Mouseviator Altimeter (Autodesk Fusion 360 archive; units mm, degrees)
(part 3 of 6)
sketch "Sketch2" plane through (0, 18.05, 0) normal (0, -1, 0) x axis (1, 0, 0)
  line L1 (-13.7221, 22.981) -> (-13.791, 23.1632)
  line L2 (-13.6429, 22.7949) -> (-13.7221, 22.981)
  line L3 (-13.562, 22.6247) -> (-13.6429, 22.7949)
  line L4 (-13.4808, 22.471) -> (-13.562, 22.6247)
  line L5 (-13.4015, 22.335) -> (-13.4808, 22.471)
  line L6 (-13.3241, 22.2142) -> (-13.4015, 22.335)
  line L7 (-13.2507, 22.1095) -> (-13.3241, 22.2142)
  line L8 (-13.1814, 22.0189) -> (-13.2507, 22.1095)
  line L9 (-13.1182, 21.9431) -> (-13.1814, 22.0189)
  line L10 (-13.0619, 21.881) -> (-13.1182, 21.9431)
  line L11 (-12.9734, 21.7944) -> (-13.0619, 21.881)
  line L12 (-12.9233, 21.7529) -> (-12.9734, 21.7944)
  line L13 (-12.8132, 21.6739) -> (-12.9233, 21.7529)
  line L14 (-12.728, 21.6001) -> (-12.8132, 21.6739)
  line L15 (-12.6608, 21.528) -> (-12.728, 21.6001)
  line L16 (-12.6113, 21.4589) -> (-12.6608, 21.528)
  line L17 (-12.5932, 21.426) -> (-12.6113, 21.4589)
  line L18 (-12.5793, 21.3943) -> (-12.5932, 21.426)
  line L19 (-12.5696, 21.364) -> (-12.5793, 21.3943)
  line L20 (-12.5641, 21.3354) -> (-12.5696, 21.364)
  line L21 (-12.5626, 21.3085) -> (-12.5641, 21.3354)
  line L22 (-12.5652, 21.2835) -> (-12.5626, 21.3085)
  line L23 (-12.5717, 21.2605) -> (-12.5652, 21.2835)
  line L24 (-12.582, 21.2398) -> (-12.5717, 21.2605)
  line L25 (-12.6628, 21.11) -> (-12.582, 21.2398)
  line L26 (-12.7577, 20.95) -> (-12.6628, 21.11)
  line L27 (-12.8488, 20.7878) -> (-12.7577, 20.95)
  line L28 (-12.9208, 20.6529) -> (-12.8488, 20.7878)
  line L29 (-12.9336, 20.6336) -> (-12.9208, 20.6529)
  line L30 (-12.9502, 20.6166) -> (-12.9336, 20.6336)
  line L31 (-12.9706, 20.6018) -> (-12.9502, 20.6166)
  line L32 (-12.9946, 20.5896) -> (-12.9706, 20.6018)
  line L33 (-13.0222, 20.5801) -> (-12.9946, 20.5896)
  line L34 (-13.0532, 20.5734) -> (-13.0222, 20.5801)
  line L35 (-13.0876, 20.5695) -> (-13.0532, 20.5734)
  line L36 (-13.1253, 20.5688) -> (-13.0876, 20.5695)
  line L37 (-13.2098, 20.5771) -> (-13.1253, 20.5688)
  line L38 (-13.3059, 20.5992) -> (-13.2098, 20.5771)
  line L39 (-13.4124, 20.6362) -> (-13.3059, 20.5992)
  line L40 (-13.5358, 20.692) -> (-13.4124, 20.6362)
  line L41 (-13.5968, 20.7146) -> (-13.5358, 20.692)
  line L42 (-13.7161, 20.748) -> (-13.5968, 20.7146)
  line L43 (-13.798, 20.7657) -> (-13.7161, 20.748)
  line L44 (-13.8952, 20.7825) -> (-13.798, 20.7657)
  line L45 (-14.0084, 20.7972) -> (-13.8952, 20.7825)
  line L46 (-14.1358, 20.8085) -> (-14.0084, 20.7972)
  line L47 (-14.279, 20.8151) -> (-14.1358, 20.8085)
  line L48 (-14.4364, 20.8157) -> (-14.279, 20.8151)
  line L49 (-14.6101, 20.8092) -> (-14.4364, 20.8157)
  line L50 (-14.798, 20.7942) -> (-14.6101, 20.8092)
  line L51 (-14.9988, 20.7697) -> (-14.798, 20.7942)
  line L52 (-15.191, 20.7383) -> (-14.9988, 20.7697)
  line L53 (-15.2969, 19.9505) -> (-15.4241, 20.0981)
  line L54 (-15.1589, 19.8027) -> (-15.2969, 19.9505)
  line L55 (-15.0246, 19.6704) -> (-15.1589, 19.8027)
  line L56 (-14.8957, 19.5538) -> (-15.0246, 19.6704)
  line L57 (-14.7747, 19.4531) -> (-14.8957, 19.5538)
  line L58 (-14.6608, 19.3661) -> (-14.7747, 19.4531)
  line L59 (-14.5559, 19.2928) -> (-14.6608, 19.3661)
  line L60 (-14.4598, 19.2313) -> (-14.5559, 19.2928)
  line L61 (-14.3745, 19.1817) -> (-14.4598, 19.2313)
  line L62 (-14.3004, 19.1426) -> (-14.3745, 19.1817)
  line L63 (-14.1875, 19.0916) -> (-14.3004, 19.1426)
  line L64 (-14.1263, 19.0696) -> (-14.1875, 19.0916)
  line L65 (-13.9959, 19.0331) -> (-14.1263, 19.0696)
  line L66 (-13.8905, 18.9929) -> (-13.9959, 19.0331)
  line L67 (-13.8027, 18.9481) -> (-13.8905, 18.9929)
  line L68 (-13.7326, 18.9001) -> (-13.8027, 18.9481)
  line L69 (-13.7043, 18.8754) -> (-13.7326, 18.9001)
  line L70 (-13.6803, 18.8503) -> (-13.7043, 18.8754)
  line L71 (-13.6609, 18.8252) -> (-13.6803, 18.8503)
  line L72 (-13.6459, 18.8002) -> (-13.6609, 18.8252)
  line L73 (-13.6354, 18.7754) -> (-13.6459, 18.8002)
  line L74 (-13.6292, 18.751) -> (-13.6354, 18.7754)
  line L75 (-13.6275, 18.7273) -> (-13.6292, 18.751)
  line L76 (-13.6301, 18.7043) -> (-13.6275, 18.7273)
  line L77 (-13.6616, 18.5547) -> (-13.6301, 18.7043)
  line L78 (-13.6961, 18.3718) -> (-13.6616, 18.5547)
  line L79 (-13.7263, 18.1883) -> (-13.6961, 18.3718)
  line L80 (-13.7478, 18.0369) -> (-13.7263, 18.1883)
  line L81 (-13.7532, 18.0144) -> (-13.7478, 18.0369)
  line L82 (-13.7629, 17.9927) -> (-13.7532, 18.0144)
  line L83 (-13.777, 17.9719) -> (-13.7629, 17.9927)
  line L84 (-13.7954, 17.9522) -> (-13.777, 17.9719)
  line L85 (-13.8181, 17.9338) -> (-13.7954, 17.9522)
  line L86 (-13.8449, 17.9168) -> (-13.8181, 17.9338)
  line L87 (-13.876, 17.9015) -> (-13.8449, 17.9168)
  line L88 (-13.9111, 17.8879) -> (-13.876, 17.9015)
  line L89 (-13.9934, 17.8668) -> (-13.9111, 17.8879)
  line L90 (-14.0912, 17.8547) -> (-13.9934, 17.8668)
  line L91 (-14.204, 17.853) -> (-14.0912, 17.8547)
  line L92 (-14.339, 17.8633) -> (-14.204, 17.853)
  line L93 (-14.4041, 17.8636) -> (-14.339, 17.8633)
  line L94 (-14.5276, 17.8542) -> (-14.4041, 17.8636)
  line L95 (-14.6106, 17.8428) -> (-14.5276, 17.8542)
  line L96 (-14.7077, 17.8254) -> (-14.6106, 17.8428)
  line L97 (-14.8191, 17.8005) -> (-14.7077, 17.8254)
  line L98 (-14.9426, 17.7675) -> (-14.8191, 17.8005)
  line L99 (-15.0795, 17.7247) -> (-14.9426, 17.7675)
  line L100 (-15.2276, 17.6715) -> (-15.0795, 17.7247)
  line L101 (-15.3886, 17.6059) -> (-15.2276, 17.6715)
  line L102 (-15.56, 17.5276) -> (-15.3886, 17.6059)
  line L103 (-15.7403, 17.4359) -> (-15.56, 17.5276)
  line L104 (-15.9103, 17.3407) -> (-15.7403, 17.4359)
  line L105 (-15.7403, 16.5641) -> (-15.9103, 16.6594)
  line L106 (-15.56, 16.4724) -> (-15.7403, 16.5641)
  line L107 (-15.3886, 16.3941) -> (-15.56, 16.4724)
  line L108 (-15.2276, 16.3285) -> (-15.3886, 16.3941)
  line L109 (-15.0795, 16.2753) -> (-15.2276, 16.3285)
  line L110 (-14.9426, 16.2325) -> (-15.0795, 16.2753)
  line L111 (-14.8191, 16.1995) -> (-14.9426, 16.2325)
  line L112 (-14.7077, 16.1746) -> (-14.8191, 16.1995)
  line L113 (-14.6106, 16.1572) -> (-14.7077, 16.1746)
  line L114 (-14.5276, 16.1458) -> (-14.6106, 16.1572)
  line L115 (-14.4041, 16.1364) -> (-14.5276, 16.1458)
  line L116 (-14.339, 16.1367) -> (-14.4041, 16.1364)
  line L117 (-14.204, 16.147) -> (-14.339, 16.1367)
  line L118 (-14.0912, 16.1453) -> (-14.204, 16.147)
  line L119 (-13.9934, 16.1333) -> (-14.0912, 16.1453)
  line L120 (-13.9111, 16.1121) -> (-13.9934, 16.1333)
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  point P994 (-7.3761, 18.9799)
  point P995 (-7.3761, 18.9799)
  point P993 (-7.3761, 15.0201)
  point P996 (-7.3761, 15.0201)
  point P992 (-4.4561, 18.9799)
  point P997 (-4.4561, 18.9799)
  point P991 (-4.4561, 15.0201)
  point P998 (-4.4561, 15.0201)
  coincident P994 P995
  coincident P993 P996
  coincident P992 P997
  coincident P991 P998
  dimension "d356" = 0.3 (= "StepperTightness")
extrude "Extrude2" cut sketch "Sketch2" to an object
hole "Hole1" HoleDepth 19.75 HoleDiameter 6.5 TipAngle 180
sketch "Sketch14" plane through (0, 0, 1) normal (0, 0, -1) x axis (1, 0, 0)
  curve K1 (-4.3957, 4.3957) -> (-3.4415, 4.9149)
  curve K2 (5.9088, 1.0419) -> (6.2165, 0)
  curve K3 (-6.2165, 0) -> (-5.9088, 1.0419)
  curve K4 (3.4415, 4.9149) -> (4.3957, 4.3957)
  curve K5 (-4.3957, -4.3957) -> (-4.9149, -3.4415)
  curve K6 (-1.0419, 5.9088) -> (0, 6.2165)
  curve K7 (0, -6.2165) -> (-1.0419, -5.9088)
  curve K8 (-4.9149, 3.4415) -> (-4.3957, 4.3957)
  curve K9 (4.3957, -4.3957) -> (3.4415, -4.9149)
  curve K10 (-5.9088, -1.0419) -> (-6.2165, 0)
  curve K11 (6.2165, 0) -> (5.9088, -1.0419)
  curve K12 (-3.4415, -4.9149) -> (-4.3957, -4.3957)
  curve K13 (4.3957, 4.3957) -> (4.9149, 3.4415)
  curve K14 (1.0419, -5.9088) -> (0, -6.2165)
  curve K15 (0, 6.2165) -> (1.0419, 5.9088)
  curve K16 (4.9149, -3.4415) -> (4.3957, -4.3957)
  curve K17 (-3.4415, 4.9149) -> (-2.4875, 5.7337)
  curve K18 (-5.7337, 2.4875) -> (-4.9149, 3.4415)
  curve K19 (-5.9088, 1.0419) -> (-5.8132, 2.2954)
  curve K20 (-5.8132, -2.2954) -> (-5.9088, -1.0419)
  curve K21 (-4.9149, -3.4415) -> (-5.7337, -2.4875)
  curve K22 (-2.4875, -5.7337) -> (-3.4415, -4.9149)
  curve K23 (-1.0419, -5.9088) -> (-2.2954, -5.8132)
  curve K24 (2.2954, -5.8132) -> (1.0419, -5.9088)
  curve K25 (3.4415, -4.9149) -> (2.4875, -5.7337)
  curve K26 (5.7337, -2.4875) -> (4.9149, -3.4415)
  curve K27 (5.9088, -1.0419) -> (5.8132, -2.2954)
  curve K28 (5.8132, 2.2954) -> (5.9088, 1.0419)
  curve K29 (4.9149, 3.4415) -> (5.7337, 2.4875)
  curve K30 (2.4875, 5.7337) -> (3.4415, 4.9149)
  curve K31 (1.0419, 5.9088) -> (2.2954, 5.8132)
  curve K32 (-2.2954, 5.8132) -> (-1.0419, 5.9088)
  arc A1 centre (0, 0) radius 6.25 clockwise from (-5.8132, 2.2954) to (-5.7337, 2.4875)
  circle C1 centre (0, 0) radius 2.9999
  circle C2 centre (0, 0.0001) radius 3.25
  arc A2 centre (0, 0) radius 6.25 clockwise from (-5.7337, -2.4875) to (-5.8132, -2.2954)
  arc A3 centre (0, 0) radius 6.25 clockwise from (-2.2954, -5.8132) to (-2.4875, -5.7337)
  arc A4 centre (0, 0) radius 6.25 clockwise from (2.4875, -5.7337) to (2.2954, -5.8132)
  arc A5 centre (0, 0) radius 6.25 clockwise from (5.8132, -2.2954) to (5.7337, -2.4875)
  arc A6 centre (0, 0) radius 6.25 clockwise from (5.7337, 2.4875) to (5.8132, 2.2954)
  arc A7 centre (0, 0) radius 6.25 clockwise from (2.2954, 5.8132) to (2.4875, 5.7337)
  arc A8 centre (0, 0) radius 6.25 clockwise from (-2.4875, 5.7337) to (-2.2954, 5.8132)
  point P1 (0, 0)
  point P27 (0, 0)
  coincident P1 P27
  dimension "d212" = 0.25
extrude "Extrude6" add sketch "Sketch14" profile of C1 along a picked direction blind 29.5
hole "Hole2" HoleDepth 19 HoleDiameter 2.8 TipAngle 180
sketch "Sketch1" plane through (0, 29.03, 0) normal (0, -1, 0) x axis (0.866, 0, -0.5)
  line L1 (1.8396, 1.2247) -> (0.9809, -1.9804)
  line L2 (-1.8396, -1.2247) -> (-0.9809, 1.9804)
  line L3 (-2.1632, -1.2731) -> (-1.2369, 2.1841)
  line L4 (2.1632, 1.2731) -> (1.2369, -2.1841)
  line L5 (-1.9, -1.9) -> (1.9, -1.9)
  line L6 (-1.9, 1.9) -> (-1.9, -1.9)
  line L7 (1.9, 1.9) -> (-1.9, 1.9)
  line L8 (1.9, -1.9) -> (1.9, 1.9)
  line L9 (-1.9, 1.9) -> (1.9, -1.9)
  line L10 (1.9, 1.9) -> (-1.9, -1.9)
  arc A1 centre (0, 0) radius 2.21 clockwise from (-0.9809, 1.9804) to (1.8396, 1.2247)
  arc A2 centre (0, 0) radius 2.21 clockwise from (0.9809, -1.9804) to (-1.8396, -1.2247)
  circle C1 centre (0, 0) radius 2.4
  arc A3 centre (0, 0) radius 2.51 clockwise from (1.2369, -2.1841) to (-2.1632, -1.2731)
  arc A4 centre (0, 0) radius 2.51 clockwise from (-1.2369, 2.1841) to (2.1632, 1.2731)
  circle C2 centre (0, 0) radius 7.5
  circle C3 centre (0, 0) radius 2.4
  arc A5 centre (0, 0) radius 2.4 clockwise from (-0.8285, -2.2525) to (-2.3965, 0.1296)
  arc A6 centre (0, 0) radius 2.4 clockwise from (-2.3965, 0.1296) to (1.086, 2.1402)
  arc A7 centre (0, 0) radius 2.4 clockwise from (1.086, 2.1402) to (2.3649, -0.4088)
  point P7 (0, 0)
  point P14 (0, 0)
  point P24 (0, 0)
  point P5 (0, 0)
  point P22 (-1.9, 1.9)
  point P23 (1.9, 1.9)
  point P21 (-1.9, -1.9)
  coincident P7 P14
  horizontal L5
  perpendicular L5 L6
  parallel L5 L7
  parallel L6 L8
  coincident L9 P24
  coincident L10 P24
  coincident P5 P24
  dimension "d222" = 0.3 (= "StepperTightness")
  dimension "d223" diameter C2 = 15
  dimension "d348" distance P22 P23 = 3.8 (= "d349")
  dimension "d349" distance P21 P22 = 3.8 (= "squareShaft + 0.3 mm")
extrude "Extrude1" new body sketch "Sketch1" profile of C1 L3 A4 A3 L4 C2 against normal blind 5
extrude "Extrude2" add sketch "Sketch1" profile of C2 L5 L6 L7 L8 along normal blind 4
fillet "Fillet1" radius 1 0.75 0.5
sketch "Sketch3" plane through (0, 7.5, 0) normal (0, 1, 0) x axis (-1, 0, 0)
  line L1 (34.7402, 0.5047) -> (34.9978, 0.3959)
  line L2 (34.481, 0.6079) -> (34.7402, 0.5047)
  line L3 (34.2324, 0.7008) -> (34.481, 0.6079)
  line L4 (33.9965, 0.7835) -> (34.2324, 0.7008)
  line L5 (33.771, 0.8572) -> (33.9965, 0.7835)
  line L6 (33.5584, 0.9219) -> (33.771, 0.8572)
  line L7 (33.3558, 0.9788) -> (33.5584, 0.9219)
  line L8 (33.045, 1.0571) -> (33.3558, 0.9788)
  line L9 (32.9935, 1.0738) -> (33.045, 1.0571)
  line L10 (32.9573, 1.0929) -> (32.9935, 1.0738)
  line L11 (32.9363, 1.1136) -> (32.9573, 1.0929)
  line L12 (32.9316, 1.1244) -> (32.9363, 1.1136)
  line L13 (32.9259, 1.2633) -> (32.9316, 1.1244)
  line L14 (32.9148, 1.5217) -> (32.9259, 1.2633)
  line L15 (32.902, 1.7801) -> (32.9148, 1.5217)
  line L16 (32.8948, 1.919) -> (32.902, 1.7801)
  line L17 (32.8986, 1.9301) -> (32.8948, 1.919)
  line L18 (32.9175, 1.9527) -> (32.8986, 1.9301)
  line L19 (32.9518, 1.975) -> (32.9175, 1.9527)
  line L20 (33.0015, 1.9964) -> (32.9518, 1.975)
  line L21 (33.3038, 2.103) -> (33.0015, 1.9964)
  line L22 (33.5003, 2.1784) -> (33.3038, 2.103)
  line L23 (33.706, 2.2624) -> (33.5003, 2.1784)
  line L24 (33.9237, 2.3567) -> (33.706, 2.2624)
  line L25 (34.151, 2.4607) -> (33.9237, 2.3567)
  line L26 (34.39, 2.5762) -> (34.151, 2.4607)
  line L27 (34.6386, 2.7029) -> (34.39, 2.5762)
  line L28 (34.885, 2.835) -> (34.6386, 2.7029)
  line L29 (34.5455, 3.7079) -> (34.8119, 3.6234)
  line L30 (34.2778, 3.7868) -> (34.5455, 3.7079)
  line L31 (34.0217, 3.8564) -> (34.2778, 3.7868)
  line L32 (33.7792, 3.9169) -> (34.0217, 3.8564)
  line L33 (33.5478, 3.9696) -> (33.7792, 3.9169)
  line L34 (33.3302, 4.0143) -> (33.5478, 3.9696)
  line L35 (33.1232, 4.0524) -> (33.3302, 4.0143)
  line L36 (32.8065, 4.1016) -> (33.1232, 4.0524)
  line L37 (32.7537, 4.1135) -> (32.8065, 4.1016)
  line L38 (32.7158, 4.1291) -> (32.7537, 4.1135)
  line L39 (32.6931, 4.1478) -> (32.7158, 4.1291)
  line L40 (32.6874, 4.1581) -> (32.6931, 4.1478)
  line L41 (32.6689, 4.2959) -> (32.6874, 4.1581)
  line L42 (32.634, 4.5523) -> (32.6689, 4.2959)
  line L43 (32.5974, 4.8083) -> (32.634, 4.5523)
  line L44 (32.5775, 4.9459) -> (32.5974, 4.8083)
  line L45 (32.5801, 4.9574) -> (32.5775, 4.9459)
  line L46 (32.5969, 4.9816) -> (32.5801, 4.9574)
  line L47 (32.629, 5.007) -> (32.5969, 4.9816)
  line L48 (32.6766, 5.0329) -> (32.629, 5.007)
  line L49 (32.9677, 5.1669) -> (32.6766, 5.0329)
  line L50 (33.1564, 5.2602) -> (32.9677, 5.1669)
  line L51 (33.3535, 5.3627) -> (33.1564, 5.2602)
  line L52 (33.5616, 5.4767) -> (33.3535, 5.3627)
  line L53 (33.7783, 5.6013) -> (33.5616, 5.4767)
  line L54 (34.0056, 5.7384) -> (33.7783, 5.6013)
  line L55 (34.2414, 5.8874) -> (34.0056, 5.7384)
  line L56 (34.4746, 6.0417) -> (34.2414, 5.8874)
  line L57 (34.056, 6.8796) -> (34.3291, 6.82)
  line L58 (33.7822, 6.9334) -> (34.056, 6.8796)
  line L59 (33.5207, 6.9791) -> (33.7822, 6.9334)
  line L60 (33.2737, 7.017) -> (33.5207, 6.9791)
  line L61 (33.0384, 7.048) -> (33.2737, 7.017)
  line L62 (32.8176, 7.0725) -> (33.0384, 7.048)
  line L63 (32.608, 7.0913) -> (32.8176, 7.0725)
  line L64 (32.2881, 7.1111) -> (32.608, 7.0913)
  line L65 (32.2344, 7.1181) -> (32.2881, 7.1111)
  line L66 (32.1953, 7.1301) -> (32.2344, 7.1181)
  line L67 (32.1709, 7.1467) -> (32.1953, 7.1301)
  line L68 (32.1643, 7.1564) -> (32.1709, 7.1467)
  line L69 (32.1331, 7.2919) -> (32.1643, 7.1564)
  line L70 (32.0748, 7.5439) -> (32.1331, 7.2919)
  line L71 (32.0147, 7.7955) -> (32.0748, 7.5439)
  line L72 (31.9821, 7.9307) -> (32.0147, 7.7955)
  line L73 (31.9837, 7.9424) -> (31.9821, 7.9307)
  line L74 (31.9982, 7.968) -> (31.9837, 7.9424)
  line L75 (32.0279, 7.9963) -> (31.9982, 7.968)
  line L76 (32.0728, 8.0264) -> (32.0279, 7.9963)
  line L77 (32.3504, 8.1868) -> (32.0728, 8.0264)
  line L78 (32.5296, 8.297) -> (32.3504, 8.1868)
  line L79 (32.7164, 8.4173) -> (32.5296, 8.297)
  line L80 (32.9131, 8.55) -> (32.7164, 8.4173)
  line L81 (33.1174, 8.6941) -> (32.9131, 8.55)
  line L82 (33.331, 8.8515) -> (33.1174, 8.6941)
  line L83 (33.5521, 9.0217) -> (33.331, 8.8515)
  line L84 (33.7701, 9.1968) -> (33.5521, 9.0217)
  line L85 (33.2759, 9.9925) -> (33.5534, 9.9584)
  line L86 (32.9984, 10.0208) -> (33.2759, 9.9925)
  line L87 (32.7338, 10.0422) -> (32.9984, 10.0208)
  line L88 (32.4843, 10.0572) -> (32.7338, 10.0422)
  line L89 (32.2472, 10.0664) -> (32.4843, 10.0572)
  line L90 (32.025, 10.0704) -> (32.2472, 10.0664)
  line L91 (31.8146, 10.0697) -> (32.025, 10.0704)
  line L92 (31.4942, 10.0599) -> (31.8146, 10.0697)
  line L93 (31.4401, 10.0619) -> (31.4942, 10.0599)
  line L94 (31.4001, 10.0703) -> (31.4401, 10.0619)
  line L95 (31.3742, 10.0845) -> (31.4001, 10.0703)
  line L96 (31.3667, 10.0936) -> (31.3742, 10.0845)
  line L97 (31.3232, 10.2257) -> (31.3667, 10.0936)
  line L98 (31.2419, 10.4712) -> (31.3232, 10.2257)
  line L99 (31.1588, 10.7162) -> (31.2419, 10.4712)
  line L100 (31.114, 10.8478) -> (31.1588, 10.7162)
  line L101 (31.1145, 10.8596) -> (31.114, 10.8478)
  line L102 (31.1265, 10.8865) -> (31.1145, 10.8596)
  line L103 (31.1534, 10.9173) -> (31.1265, 10.8865)
  line L104 (31.1954, 10.9515) -> (31.1534, 10.9173)
  line L105 (31.457, 11.1368) -> (31.1954, 10.9515)
  line L106 (31.6253, 11.2631) -> (31.457, 11.1368)
  line L107 (31.8001, 11.4001) -> (31.6253, 11.2631)
  line L108 (31.9838, 11.5504) -> (31.8001, 11.4001)
  line L109 (32.1739, 11.7127) -> (31.9838, 11.5504)
  line L110 (32.3721, 11.8892) -> (32.1739, 11.7127)
  line L111 (32.5766, 12.079) -> (32.3721, 11.8892)
  line L112 (32.7775, 12.2735) -> (32.5766, 12.079)
  line L113 (32.212, 13.0202) -> (32.4914, 13.0118)
  line L114 (31.933, 13.0228) -> (32.212, 13.0202)
  line L115 (31.6676, 13.0197) -> (31.933, 13.0228)
  line L116 (31.4177, 13.0115) -> (31.6676, 13.0197)
  line L117 (31.1808, 12.9988) -> (31.4177, 13.0115)
  line L118 (30.9593, 12.9823) -> (31.1808, 12.9988)
  line L119 (30.7498, 12.9623) -> (30.9593, 12.9823)
  line L120 (30.4316, 12.923) -> (30.7498, 12.9623)
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  point P1 (0, 0)
  point P2043 (25, 0)
  horizontal P1 P2043
  dimension "d230" diameter = 3.15 (= "MagnetDiameter + 0.15 mm")
  dimension "d231" distance P1 P2043 = 25
extrude "Extrude4" cut sketch "Sketch3" against normal blind 1.5
as_built_joint "As-built1" OffsetX 0 OffsetY 0 OffsetZ 0 AngleZ 0
as_built_joint "As-built2"
ground "Ground1"
fillet "Fillet1" radius 1
fillet "Fillet1" radius 1
sketch "Sketch3" plane through (0, 10.05, 0) normal (0, -1, 0) x axis (-1, 0, 0)
  curve K1
  curve K2
  curve K3
  curve K4
  line L1 (4.5346, 8.726) -> (4.7021, 8.8255)
  line L2 (5.2921, 8.4849) -> (5.2896, 8.2901)
  line L3 (5.2896, 8.2901) -> (5.2789, 8.0881)
  line L4 (5.2789, 8.0881) -> (5.261, 7.9005)
  line L5 (5.261, 7.9005) -> (5.2373, 7.7283)
  line L6 (5.2373, 7.7283) -> (5.2093, 7.5734)
  line L7 (5.2093, 7.5734) -> (5.1779, 7.4335)
  line L8 (5.1779, 7.4335) -> (5.1448, 7.3099)
  line L9 (5.1448, 7.3099) -> (5.1106, 7.2011)
  line L10 (5.1106, 7.2011) -> (5.0771, 7.1083)
  line L11 (5.0771, 7.1083) -> (5.0455, 7.0307)
  line L12 (5.0455, 7.0307) -> (4.9919, 6.919)
  line L13 (4.9919, 6.919) -> (4.9591, 6.8628)
  line L14 (4.9591, 6.8628) -> (4.8826, 6.751)
  line L15 (4.8826, 6.751) -> (4.8277, 6.6525)
  line L16 (4.8277, 6.6525) -> (4.7893, 6.5617)
  line L17 (4.7893, 6.5617) -> (4.7664, 6.4799)
  line L18 (4.7664, 6.4799) -> (4.7606, 6.4427)
  line L19 (4.7606, 6.4427) -> (4.7584, 6.4082)
  line L20 (4.7584, 6.4082) -> (4.7597, 6.3765)
  line L21 (4.7597, 6.3765) -> (4.7643, 6.3476)
  line L22 (4.7643, 6.3476) -> (4.7721, 6.3219)
  line L23 (4.7721, 6.3219) -> (4.7831, 6.2992)
  line L24 (4.7831, 6.2992) -> (4.797, 6.2799)
  line L25 (4.797, 6.2799) -> (4.8138, 6.264)
  line L26 (4.8138, 6.264) -> (4.9341, 6.1697)
  line L27 (4.9341, 6.1697) -> (5.078, 6.0518)
  line L28 (5.078, 6.0518) -> (5.2191, 5.9305)
  line L29 (5.2191, 5.9305) -> (5.3329, 5.8284)
  line L30 (5.3329, 5.8284) -> (5.3515, 5.8146)
  line L31 (5.3515, 5.8146) -> (5.373, 5.8043)
  line L32 (5.373, 5.8043) -> (5.3971, 5.7974)
  line L33 (5.3971, 5.7974) -> (5.4239, 5.7941)
  line L34 (5.4239, 5.7941) -> (5.4531, 5.7946)
  line L35 (5.4531, 5.7946) -> (5.4845, 5.7989)
  line L36 (5.4845, 5.7989) -> (5.5182, 5.8071)
  line L37 (5.5182, 5.8071) -> (5.5538, 5.8192)
  line L38 (5.5538, 5.8192) -> (5.6304, 5.8559)
  line L39 (5.6304, 5.8559) -> (5.7131, 5.9096)
  line L40 (5.7131, 5.9096) -> (5.8006, 5.9808)
  line L41 (5.8006, 5.9808) -> (5.8974, 6.0755)
  line L42 (5.8974, 6.0755) -> (5.9471, 6.1175)
  line L43 (5.9471, 6.1175) -> (6.0477, 6.1897)
  line L44 (6.0477, 6.1897) -> (6.1186, 6.2344)
  line L45 (6.1186, 6.2344) -> (6.2042, 6.2834)
  line L46 (6.2042, 6.2834) -> (6.3055, 6.3359)
  line L47 (6.3055, 6.3359) -> (6.4214, 6.3901)
  line L48 (6.4214, 6.3901) -> (6.5538, 6.4453)
  line L49 (6.5538, 6.4453) -> (6.7014, 6.4997)
  line L50 (6.7014, 6.4997) -> (6.8669, 6.553)
  line L51 (6.8669, 6.553) -> (7.0486, 6.6032)
  line L52 (7.0486, 6.6032) -> (7.2456, 6.6488)
  line L53 (7.2456, 6.6488) -> (7.437, 6.6851)
  line L54 (7.8749, 6.1632) -> (7.806, 5.981)
  line L55 (7.806, 5.981) -> (7.7268, 5.7948)
  line L56 (7.7268, 5.7948) -> (7.6459, 5.6247)
  line L57 (7.6459, 5.6247) -> (7.5647, 5.471)
  line L58 (7.5647, 5.471) -> (7.4854, 5.335)
  line L59 (7.4854, 5.335) -> (7.408, 5.2142)
  line L60 (7.408, 5.2142) -> (7.3346, 5.1095)
  line L61 (7.3346, 5.1095) -> (7.2653, 5.0189)
  line L62 (7.2653, 5.0189) -> (7.2021, 4.9431)
  line L63 (7.2021, 4.9431) -> (7.1458, 4.881)
  line L64 (7.1458, 4.881) -> (7.0573, 4.7944)
  line L65 (7.0573, 4.7944) -> (7.0072, 4.7529)
  line L66 (7.0072, 4.7529) -> (6.8972, 4.6739)
  line L67 (6.8972, 4.6739) -> (6.8119, 4.6001)
  line L68 (6.8119, 4.6001) -> (6.7447, 4.528)
  line L69 (6.7447, 4.528) -> (6.6952, 4.4589)
  line L70 (6.6952, 4.4589) -> (6.6771, 4.426)
  line L71 (6.6771, 4.426) -> (6.6632, 4.3943)
  line L72 (6.6632, 4.3943) -> (6.6535, 4.364)
  line L73 (6.6535, 4.364) -> (6.648, 4.3353)
  line L74 (6.648, 4.3353) -> (6.6465, 4.3084)
  line L75 (6.6465, 4.3084) -> (6.6491, 4.2834)
  line L76 (6.6491, 4.2834) -> (6.6556, 4.2605)
  line L77 (6.6556, 4.2605) -> (6.6659, 4.2398)
  line L78 (6.6659, 4.2398) -> (6.7467, 4.11)
  line L79 (6.7467, 4.11) -> (6.8416, 3.95)
  line L80 (6.8416, 3.95) -> (6.9327, 3.7878)
  line L81 (6.9327, 3.7878) -> (7.0047, 3.6529)
  line L82 (7.0047, 3.6529) -> (7.0175, 3.6336)
  line L83 (7.0175, 3.6336) -> (7.0341, 3.6166)
  line L84 (7.0341, 3.6166) -> (7.0545, 3.6018)
  line L85 (7.0545, 3.6018) -> (7.0785, 3.5896)
  line L86 (7.0785, 3.5896) -> (7.1061, 3.5801)
  line L87 (7.1061, 3.5801) -> (7.1371, 3.5733)
  line L88 (7.1371, 3.5733) -> (7.1715, 3.5695)
  line L89 (7.1715, 3.5695) -> (7.2092, 3.5688)
  line L90 (7.2092, 3.5688) -> (7.2937, 3.5771)
  line L91 (7.2937, 3.5771) -> (7.3898, 3.5992)
  line L92 (7.3898, 3.5992) -> (7.4963, 3.6361)
  line L93 (7.4963, 3.6361) -> (7.6197, 3.692)
  line L94 (7.6197, 3.692) -> (7.6807, 3.7146)
  line L95 (7.6807, 3.7146) -> (7.8, 3.748)
  line L96 (7.8, 3.748) -> (7.8819, 3.7657)
  line L97 (7.8819, 3.7657) -> (7.9791, 3.7825)
  line L98 (7.9791, 3.7825) -> (8.0923, 3.7972)
  line L99 (8.0923, 3.7972) -> (8.2197, 3.8084)
  line L100 (8.2197, 3.8084) -> (8.3629, 3.815)
  line L101 (8.3629, 3.815) -> (8.5203, 3.8157)
  line L102 (8.5203, 3.8157) -> (8.694, 3.8092)
  line L103 (8.694, 3.8092) -> (8.8819, 3.7942)
  line L104 (8.8819, 3.7942) -> (9.0827, 3.7697)
  line L105 (9.0827, 3.7697) -> (9.275, 3.7383)
  line L106 (9.508, 3.0981) -> (9.3808, 2.9505)
  line L107 (9.3808, 2.9505) -> (9.2428, 2.8026)
  line L108 (9.2428, 2.8026) -> (9.1085, 2.6704)
  line L109 (9.1085, 2.6704) -> (8.9796, 2.5538)
  line L110 (8.9796, 2.5538) -> (8.8586, 2.4531)
  line L111 (8.8586, 2.4531) -> (8.7447, 2.3661)
  line L112 (8.7447, 2.3661) -> (8.6398, 2.2928)
  line L113 (8.6398, 2.2928) -> (8.5437, 2.2313)
  line L114 (8.5437, 2.2313) -> (8.4584, 2.1817)
  line L115 (8.4584, 2.1817) -> (8.3843, 2.1426)
  line L116 (8.3843, 2.1426) -> (8.2714, 2.0915)
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  dimension "d246" Text1-Height = 2
extrude "Extrude4" cut sketch "Sketch3" blind -1
sketch "Gear" plane through (0, 14.95, 0) normal (0, 1, 0) x axis (-1, 0, 0)
  curve K1
  curve K2
  curve K3
  curve K4
  line L1 (-15.8921, -14.8998) -> (-16.0154, -14.7489)
  line L2 (-15.1569, -14.5976) -> (-15.2212, -14.7815)
  line L3 (-15.0979, -14.4041) -> (-15.1569, -14.5976)
  line L4 (-15.0505, -14.2217) -> (-15.0979, -14.4041)
  line L5 (-15.0139, -14.0518) -> (-15.0505, -14.2217)
  line L6 (-14.9872, -13.8966) -> (-15.0139, -14.0518)
  line L7 (-14.9689, -13.7544) -> (-14.9872, -13.8966)
  line L8 (-14.9578, -13.627) -> (-14.9689, -13.7544)
  line L9 (-14.9526, -13.513) -> (-14.9578, -13.627)
  line L10 (-14.9523, -13.4144) -> (-14.9526, -13.513)
  line L11 (-14.9556, -13.3306) -> (-14.9523, -13.4144)
  line L12 (-14.9677, -13.2073) -> (-14.9556, -13.3306)
  line L13 (-14.9793, -13.1434) -> (-14.9677, -13.2073)
  line L14 (-15.0129, -13.0121) -> (-14.9793, -13.1434)
  line L15 (-15.0308, -12.9008) -> (-15.0129, -13.0121)
  line L16 (-15.0359, -12.8023) -> (-15.0308, -12.9008)
  line L17 (-15.0294, -12.7176) -> (-15.0359, -12.8023)
  line L18 (-15.0221, -12.6807) -> (-15.0294, -12.7176)
  line L19 (-15.0124, -12.6475) -> (-15.0221, -12.6807)
  line L20 (-15.0004, -12.6181) -> (-15.0124, -12.6475)
  line L21 (-14.9862, -12.5926) -> (-15.0004, -12.6181)
  line L22 (-14.97, -12.5711) -> (-14.9862, -12.5926)
  line L23 (-14.952, -12.5535) -> (-14.97, -12.5711)
  line L24 (-14.9323, -12.5402) -> (-14.952, -12.5535)
  line L25 (-14.9111, -12.5309) -> (-14.9323, -12.5402)
  line L26 (-14.7657, -12.4835) -> (-14.9111, -12.5309)
  line L27 (-14.5902, -12.4219) -> (-14.7657, -12.4835)
  line L28 (-14.4161, -12.3562) -> (-14.5902, -12.4219)
  line L29 (-14.2742, -12.2991) -> (-14.4161, -12.3562)
  line L30 (-14.252, -12.2926) -> (-14.2742, -12.2991)
  line L31 (-14.2283, -12.2902) -> (-14.252, -12.2926)
  line L32 (-14.2033, -12.292) -> (-14.2283, -12.2902)
  line L33 (-14.177, -12.2981) -> (-14.2033, -12.292)
  line L34 (-14.1498, -12.3085) -> (-14.177, -12.2981)
  line L35 (-14.1217, -12.3233) -> (-14.1498, -12.3085)
  line L36 (-14.0929, -12.3425) -> (-14.1217, -12.3233)
  line L37 (-14.0635, -12.3661) -> (-14.0929, -12.3425)
  line L38 (-14.0041, -12.4268) -> (-14.0635, -12.3661)
  line L39 (-13.9447, -12.5055) -> (-14.0041, -12.4268)
  line L40 (-13.8869, -12.6023) -> (-13.9447, -12.5055)
  line L41 (-13.8283, -12.7244) -> (-13.8869, -12.6023)
  line L42 (-13.796, -12.7809) -> (-13.8283, -12.7244)
  line L43 (-13.7261, -12.8831) -> (-13.796, -12.7809)
  line L44 (-13.6747, -12.9494) -> (-13.7261, -12.8831)
  line L45 (-13.6111, -13.0247) -> (-13.6747, -12.9494)
  line L46 (-13.5339, -13.1087) -> (-13.6111, -13.0247)
  line L47 (-13.4435, -13.1992) -> (-13.5339, -13.1087)
  line L48 (-13.338, -13.2964) -> (-13.4435, -13.1992)
  line L49 (-13.2178, -13.3981) -> (-13.338, -13.2964)
  line L50 (-13.0806, -13.5047) -> (-13.2178, -13.3981)
  line L51 (-12.9271, -13.614) -> (-13.0806, -13.5047)
  line L52 (-12.7575, -13.7243) -> (-12.9271, -13.614)
  line L53 (-12.59, -13.8238) -> (-12.7575, -13.7243)
  line L54 (-12.0025, -13.2884) -> (-12, -13.4832)
  line L55 (-12.0132, -13.0864) -> (-12.0025, -13.2884)
  line L56 (-12.0311, -12.8988) -> (-12.0132, -13.0864)
  line L57 (-12.0548, -12.7266) -> (-12.0311, -12.8988)
  line L58 (-12.0828, -12.5717) -> (-12.0548, -12.7266)
  line L59 (-12.1142, -12.4318) -> (-12.0828, -12.5717)
  line L60 (-12.1474, -12.3082) -> (-12.1142, -12.4318)
  line L61 (-12.1815, -12.1993) -> (-12.1474, -12.3082)
  line L62 (-12.215, -12.1066) -> (-12.1815, -12.1993)
  line L63 (-12.2466, -12.0289) -> (-12.215, -12.1066)
  line L64 (-12.3002, -11.9173) -> (-12.2466, -12.0289)
  line L65 (-12.333, -11.8611) -> (-12.3002, -11.9173)
  line L66 (-12.4095, -11.7493) -> (-12.333, -11.8611)
  line L67 (-12.4644, -11.6508) -> (-12.4095, -11.7493)
  line L68 (-12.5028, -11.56) -> (-12.4644, -11.6508)
  line L69 (-12.5257, -11.4782) -> (-12.5028, -11.56)
  line L70 (-12.5315, -11.441) -> (-12.5257, -11.4782)
  line L71 (-12.5337, -11.4065) -> (-12.5315, -11.441)
  line L72 (-12.5325, -11.3747) -> (-12.5337, -11.4065)
  line L73 (-12.5278, -11.3459) -> (-12.5325, -11.3747)
  line L74 (-12.52, -11.3201) -> (-12.5278, -11.3459)
  line L75 (-12.509, -11.2975) -> (-12.52, -11.3201)
  line L76 (-12.4951, -11.2782) -> (-12.509, -11.2975)
  line L77 (-12.4783, -11.2623) -> (-12.4951, -11.2782)
  line L78 (-12.358, -11.168) -> (-12.4783, -11.2623)
  line L79 (-12.2141, -11.05) -> (-12.358, -11.168)
  line L80 (-12.073, -10.9288) -> (-12.2141, -11.05)
  line L81 (-11.9592, -10.8267) -> (-12.073, -10.9288)
  line L82 (-11.9406, -10.8129) -> (-11.9592, -10.8267)
  line L83 (-11.9191, -10.8025) -> (-11.9406, -10.8129)
  line L84 (-11.895, -10.7957) -> (-11.9191, -10.8025)
  line L85 (-11.8682, -10.7924) -> (-11.895, -10.7957)
  line L86 (-11.839, -10.7929) -> (-11.8682, -10.7924)
  line L87 (-11.8076, -10.7972) -> (-11.839, -10.7929)
  line L88 (-11.7739, -10.8054) -> (-11.8076, -10.7972)
  line L89 (-11.7383, -10.8175) -> (-11.7739, -10.8054)
  line L90 (-11.6617, -10.8542) -> (-11.7383, -10.8175)
  line L91 (-11.579, -10.9079) -> (-11.6617, -10.8542)
  line L92 (-11.4915, -10.979) -> (-11.579, -10.9079)
  line L93 (-11.3947, -11.0738) -> (-11.4915, -10.979)
  line L94 (-11.3451, -11.1158) -> (-11.3947, -11.0738)
  line L95 (-11.2444, -11.188) -> (-11.3451, -11.1158)
  line L96 (-11.1735, -11.2326) -> (-11.2444, -11.188)
  line L97 (-11.0879, -11.2817) -> (-11.1735, -11.2326)
  line L98 (-10.9866, -11.3342) -> (-11.0879, -11.2817)
  line L99 (-10.8707, -11.3884) -> (-10.9866, -11.3342)
  line L100 (-10.7384, -11.4435) -> (-10.8707, -11.3884)
  line L101 (-10.5907, -11.498) -> (-10.7384, -11.4435)
  line L102 (-10.4252, -11.5513) -> (-10.5907, -11.498)
  line L103 (-10.2436, -11.6015) -> (-10.4252, -11.5513)
  line L104 (-10.0465, -11.6471) -> (-10.2436, -11.6015)
  line L105 (-9.8551, -11.6834) -> (-10.0465, -11.6471)
  line L106 (-9.4861, -10.9793) -> (-9.4172, -11.1615)
  line L107 (-9.5653, -10.7931) -> (-9.4861, -10.9793)
  line L108 (-9.6462, -10.623) -> (-9.5653, -10.7931)
  line L109 (-9.7274, -10.4693) -> (-9.6462, -10.623)
  line L110 (-9.8067, -10.3333) -> (-9.7274, -10.4693)
  line L111 (-9.8841, -10.2125) -> (-9.8067, -10.3333)
  line L112 (-9.9575, -10.1078) -> (-9.8841, -10.2125)
  line L113 (-10.0268, -10.0172) -> (-9.9575, -10.1078)
  line L114 (-10.09, -9.9414) -> (-10.0268, -10.0172)
  line L115 (-10.1463, -9.8793) -> (-10.09, -9.9414)
  line L116 (-10.2349, -9.7927) -> (-10.1463, -9.8793)
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  dimension "d249" Text1-Height = 4
sketch "Trace DXF" plane through (0, 3.5, 0) normal (0, -1, 0) x axis (1, 0, 0)
  line L1 (32.6235, 7.6129) -> (25.3452, 5.7982)
  line L2 (25.3452, -5.7982) -> (32.6737, -7.3944)
  curve K1 (-41.4655, 20.5361) -> (-41.4365, 21.0784)
  line L3 (-41.4655, -28.9018) -> (-41.4655, 20.5361)
  line L4 (21.3665, -41.4655) -> (-28.9018, -41.4655)
  curve K2 (21.9088, -41.4365) -> (21.3665, -41.4655)
  line L5 (33.6166, -37.0564) -> (23.2139, -41.1177)
  line L6 (41.1157, -22.3885) -> (36.4994, -34.1766)
  line L7 (41.4655, 20.5361) -> (41.4655, -20.5361)
  line L8 (36.4994, 34.1766) -> (41.1157, 22.3885)
  line L9 (26.5251, 40.8618) -> (33.6166, 37.0564)
  line L10 (-24.1331, 41.4655) -> (24.1231, 41.4655)
  line L11 (-34.1546, 36.8093) -> (-26.5185, 40.8706)
  line L12 (-41.1157, 22.3885) -> (-36.4994, 34.1766)
  circle C1 centre (-30.9024, -30.9024) radius 3.25
  circle C2 centre (36.96, -18.76) radius 1.4
  arc A1 centre (0, 0) radius 33.5 clockwise from (32.6235, 7.6129) to (32.6737, -7.3944)
  arc A2 centre (0, 0) radius 26 clockwise from (25.3452, 5.7982) to (25.3452, -5.7982)
  circle C3 centre (31.4309, 31.4309) radius 2.159
  circle C4 centre (-31.4309, 31.4309) radius 2.159
  circle C5 centre (-0.2224, 0.034) radius 5.25
  circle C6 centre (31.4309, -31.4309) radius 2.159
  circle C7 centre (36.96, 18.76) radius 1.4
  circle C8 centre (18.76, 36.96) radius 1.4
  circle C9 centre (-18.76, 36.96) radius 1.4
  circle C10 centre (-36.96, 18.76) radius 1.4
  circle C11 centre (18.76, -36.96) radius 1.4
  arc A3 centre (-36.3855, 20.5361) radius 5.08 clockwise from (-41.4365, 21.0784) to (-41.1157, 22.3885)
  arc A4 centre (-28.9018, -28.9018) radius 12.5637 clockwise from (-28.9018, -41.4655) to (-41.4655, -28.9018)
  arc A5 centre (21.3665, -36.3855) radius 5.08 clockwise from (23.2139, -41.1177) to (21.9088, -41.4365)
  arc A6 centre (31.7692, -32.3242) radius 5.08 clockwise from (36.4994, -34.1766) to (33.6166, -37.0564)
  arc A7 centre (36.3855, -20.5361) radius 5.08 clockwise from (41.4655, -20.5361) to (41.1157, -22.3885)
  arc A8 centre (36.3855, 20.5361) radius 5.08 clockwise from (41.1157, 22.3885) to (41.4655, 20.5361)
  arc A9 centre (31.7692, 32.3242) radius 5.08 clockwise from (33.6166, 37.0564) to (36.4994, 34.1766)
  arc A10 centre (24.1231, 36.3855) radius 5.08 clockwise from (24.1231, 41.4655) to (26.5251, 40.8618)
  arc A11 centre (-24.1331, 36.3855) radius 5.08 clockwise from (-26.5185, 40.8706) to (-24.1331, 41.4655)
  arc A12 centre (-31.7692, 32.3242) radius 5.08 clockwise from (-36.4994, 34.1766) to (-34.1546, 36.8093)
extrude "Extrude5" sketch "Gear" to an object
sketch "Trace DXF" plane through (0, 2, 0) normal (0, -1, 0) x axis (1, 0, 0)
  line L1 (-3.7809, 16.061) -> (-2.1183, 19.2337)
  line L2 (-2.1183, 19.2337) -> (0.195, 16.4988)
  line L3 (-2.1183, 19.2337) -> (-3.7809, 16.061)
  line L4 (0.195, 16.4988) -> (-2.1183, 19.2337)
  line L5 (5.7809, -15.4542) -> (2.6381, -7.2245)
  line L6 (-1.0026, -7.6255) -> (-2.2791, -16.3418)
  line L7 (-2.2791, -16.3418) -> (-1.0026, -7.6255)
  line L8 (2.6381, -7.2245) -> (5.7809, -15.4542)
  circle C1 centre (0, 0) radius 4
  arc A1 centre (0, 0) radius 16.5 clockwise from (0.195, 16.4988) to (5.7809, -15.4542)
  circle C2 centre (0, 0) radius 4
  arc A2 centre (0, 0) radius 16.5 clockwise from (-2.2791, -16.3418) to (-3.7809, 16.061)
  arc A3 centre (-0.1807, -0.3465) radius 7.3252 clockwise from (0.8371, -7.6007) to (-1.0026, -7.6255)
  arc A4 centre (0.2518, -0.2989) radius 7.3252 clockwise from (2.6381, -7.2245) to (0.8371, -7.6007)
  arc A5 centre (-0.1807, -0.3465) radius 7.3252 clockwise from (0.8371, -7.6007) to (-1.0026, -7.6255)
  arc A6 centre (0, 0) radius 16.5 clockwise from (0.195, 16.4988) to (5.7809, -15.4542)
  arc A7 centre (0.2518, -0.2989) radius 7.3252 clockwise from (2.6381, -7.2245) to (0.8371, -7.6007)
  arc A8 centre (0, 0) radius 16.5 clockwise from (-2.2791, -16.3418) to (-3.7809, 16.061)
sketch "Trace DXF" plane through (0, 0, 0) normal (0, -1, 0) x axis (1, 0, 0)
  line L1 (-16.2012, 11.5652) -> (-15.8275, 12.0716)
  line L2 (-12.2851, 5.9884) -> (-16.2012, 11.5652)
  line L3 (-10.3599, 6.4055) -> (-12.2851, 5.9884)
  line L4 (-3.6581, 0.5553) -> (-10.3599, 6.4055)
  line L5 (4.2996, -4.574) -> (1.6831, -3.295)
  line L6 (3.6448, -0.6368) -> (5.6383, -2.76)
  line L7 (-9.1751, 8.011) -> (-1.6091, 3.3318)
  line L8 (-9.344, 9.9736) -> (-9.1751, 8.011)
  line L9 (-15.8275, 12.0716) -> (-9.344, 9.9736)
  line L10 (1.6831, -3.295) -> (2.2271, -3.5609)
  line L11 (4.0592, -1.0783) -> (3.6448, -0.6368)
  line L12 (-1.6091, 3.3318) -> (-2.1016, 3.6364)
  line L13 (-4.0943, 0.9361) -> (-3.6581, 0.5553)
  line L14 (5.6383, -2.76) -> (4.0592, -1.0783)
  line L15 (4.2996, -4.574) -> (2.2271, -3.5609)
  line L16 (-4.0943, 0.9361) -> (-10.3599, 6.4055)
  line L17 (-10.3599, 6.4055) -> (-12.2851, 5.9884)
  line L18 (-12.2851, 5.9884) -> (-16.2012, 11.5652)
  line L19 (-16.2012, 11.5652) -> (-15.8275, 12.0716)
  line L20 (-9.344, 9.9736) -> (-15.8275, 12.0716)
  line L21 (-9.1751, 8.011) -> (-9.344, 9.9736)
  line L22 (-2.1016, 3.6364) -> (-9.1751, 8.011)
  circle C1 centre (0, 0) radius 2.7
  arc A1 centre (0, 0) radius 3.7 clockwise from (1.6831, -3.295) to (-3.6581, 0.5553)
  arc A2 centre (6.6381, -4.8988) radius 2.361 clockwise from (5.6383, -2.76) to (4.2996, -4.574)
  arc A3 centre (0, 0) radius 3.7 clockwise from (-1.6091, 3.3318) to (3.6448, -0.6368)
  arc A4 centre (0, 0) radius 3.7 clockwise from (-3.7, 0) to (-3.6581, 0.5553)
  arc A5 centre (0, 0) radius 3.7 clockwise from (-1.6091, 3.3318) to (3.6448, -0.6368)
  arc A6 centre (0, 0) radius 3.7 clockwise from (1.6831, -3.295) to (-3.7, 0)
  circle C2 centre (0, 0) radius 2.7
  arc A7 centre (6.6381, -4.8988) radius 2.361 clockwise from (5.6383, -2.76) to (4.2996, -4.574)
sketch "Trace DXF" plane through (0, -2, 0) normal (0, -1, 0) x axis (1, 0, 0)
  line L1 (-2.0106, 1.3105) -> (-2.2265, 4.9919)
  line L2 (0.4929, -24.5741) -> (-0.4929, -24.5741)
  line L3 (1.8437, -1.5365) -> (0.4929, -24.5741)
  line L4 (1.8005, -2.2734) -> (1.8437, -1.5365)
  line L5 (-2.0538, 2.0474) -> (-2.0106, 1.3105)
  line L6 (-2.0538, 2.0474) -> (-2.2265, 4.9919)
  line L7 (0.4929, -24.5741) -> (1.8005, -2.2734)
  line L8 (-0.4929, -24.5741) -> (0.4929, -24.5741)
  line L9 (-0.4929, -24.5741) -> (-1.8437, -1.5365)
  line L10 (2.2265, 4.9919) -> (2.0106, 1.3105)
  line L11 (-1.8437, -1.5365) -> (-1.8005, -2.2734)
  line L12 (2.0106, 1.3105) -> (2.0538, 2.0474)
  line L13 (-0.4929, -24.5741) -> (-1.8005, -2.2734)
  line L14 (2.0538, 2.0474) -> (2.2265, 4.9919)
  arc A1 centre (0, 4.9919) radius 2.2265 clockwise from (-2.2265, 4.9919) to (2.2265, 4.9919)
  arc A2 centre (0, 4.9919) radius 2.2265 clockwise from (-2.2265, 4.9919) to (2.2265, 4.9919)
  arc A3 centre (0, 0) radius 2.4 clockwise from (-1.8437, -1.5365) to (-2.0106, 1.3105)
  arc A4 centre (0, 0) radius 2.4 clockwise from (2.0106, 1.3105) to (1.8437, -1.5365)
  arc A5 centre (0, 0) radius 2.4 clockwise from (-2.4, 0) to (-2.0106, 1.3105)
  arc A6 centre (0, 0) radius 2.4 clockwise from (2.0106, 1.3105) to (1.8437, -1.5365)
  arc A7 centre (0, 0) radius 2.4 clockwise from (-1.8437, -1.5365) to (-2.4, 0)
sketch "Sketch3" plane through (0, 29.03, 0) normal (0, 1, 0) x axis (-1, 0, 0)
  line L1 (-1.75, -1.75) -> (1.75, -1.75)
  line L2 (-1.75, 1.75) -> (-1.75, -1.75)
  line L3 (1.75, 1.75) -> (-1.75, 1.75)
  line L4 (1.75, -1.75) -> (1.75, 1.75)
  line L5 (-1.75, 1.75) -> (1.75, -1.75)
  line L6 (1.75, 1.75) -> (-1.75, -1.75)
  circle C1 centre (0, 0) radius 2.4
  point P7 (0, 0)
  point P1 (0, 0)
  point P5 (-1.75, 1.75)
  point P6 (1.75, 1.75)
  point P3 (1.75, -1.75)
  horizontal L1
  perpendicular L1 L2
  parallel L1 L3
  parallel L2 L4
  coincident L5 P7
  coincident L6 P7
  coincident P1 P7
  dimension "d351" distance P5 P6 = 3.5 (= "squareShaft")
  dimension "d352" distance P3 P6 = 3.5 (= "d351")
extrude "Extrude3" cut sketch "Sketch3" profile of C1 L1 L2 L3 L4 against normal blind 5
decal "Decal1"
decal "Decal1"
sketch "Stepper Ear Pipe Outline" plane through (0, 39, 0) normal (0, 1, 0) x axis (-1, 0, 0)
  line L1 (-41.4655, -13.9983) -> (-36.1766, -13.9983)
  line L2 (-41.4655, -20.5361) -> (-41.4655, -13.9983)
  line L3 (-36.4994, -34.1766) -> (-41.1157, -22.3885)
  line L4 (-23.2139, -41.1177) -> (-33.6166, -37.0564)
  curve K1 (-21.3665, -41.4655) -> (-21.9088, -41.4365)
  line L5 (28.9018, -41.4655) -> (-21.3665, -41.4655)
  line L6 (41.4655, 20.5361) -> (41.4655, -28.9018)
  curve K2 (41.4365, 21.0784) -> (41.4655, 20.5361)
  line L7 (36.4994, 34.1766) -> (41.1157, 22.3885)
  line L8 (26.5185, 40.8706) -> (34.1546, 36.8093)
  line L9 (14.9161, 41.4655) -> (24.1331, 41.4655)
  line L10 (14.9161, 35.8845) -> (14.9161, 41.4655)
  line L11 (-3.0839, 41.4655) -> (-3.0839, 35.8845)
  line L12 (-24.1231, 41.4655) -> (-3.0839, 41.4655)
  line L13 (-33.6166, 37.0564) -> (-26.5251, 40.8618)
  line L14 (-41.1157, 22.3885) -> (-36.4994, 34.1766)
  line L15 (-41.4655, 4.0017) -> (-41.4655, 20.5361)
  line L16 (-36.1766, 4.0017) -> (-41.4655, 4.0017)
  line L17 (12.6119, 7.2025) -> (15.0791, 9.6697)
  line L18 (20.0288, 4.7199) -> (17.5616, 2.2528)
  line L19 (-2.2528, -17.5616) -> (-4.7199, -20.0288)
  line L20 (-9.6697, -15.0791) -> (-7.2025, -12.6119)
  arc A1 centre (-36.3855, -20.5361) radius 5.08 clockwise from (-41.1157, -22.3885) to (-41.4655, -20.5361)
  arc A2 centre (-31.7692, -32.3242) radius 5.08 clockwise from (-33.6166, -37.0564) to (-36.4994, -34.1766)
  arc A3 centre (-21.3665, -36.3855) radius 5.08 clockwise from (-21.9088, -41.4365) to (-23.2139, -41.1177)
  arc A4 centre (28.9018, -28.9018) radius 12.5637 clockwise from (41.4655, -28.9018) to (28.9018, -41.4655)
  arc A5 centre (36.3855, 20.5361) radius 5.08 clockwise from (41.1157, 22.3885) to (41.4365, 21.0784)
  arc A6 centre (31.7692, 32.3242) radius 5.08 clockwise from (34.1546, 36.8093) to (36.4994, 34.1766)
  arc A7 centre (24.1331, 36.3855) radius 5.08 clockwise from (24.1331, 41.4655) to (26.5185, 40.8706)
  arc A8 centre (5.9161, 24.325) radius 14.65 clockwise from (14.9161, 35.8845) to (-3.0839, 35.8845)
  arc A9 centre (-24.1231, 36.3855) radius 5.08 clockwise from (-26.5251, 40.8618) to (-24.1231, 41.4655)
  arc A10 centre (-31.7692, 32.3242) radius 5.08 clockwise from (-36.4994, 34.1766) to (-33.6166, 37.0564)
  arc A11 centre (-36.3855, 20.5361) radius 5.08 clockwise from (-41.4655, 20.5361) to (-41.1157, 22.3885)
  arc A12 centre (-24.6171, -4.9983) radius 14.65 clockwise from (-36.1766, 4.0017) to (-36.1766, -13.9983)
  circle C1 centre (17.5539, 7.1948) radius 1.4
  circle C2 centre (-7.1948, -17.5539) radius 1.4
  circle C3 centre (30.9023, -30.9023) radius 5.5
  circle C4 centre (-18.76, 36.96) radius 1
  circle C5 centre (31.4309, 31.4309) radius 2.159
  circle C6 centre (-31.4309, -31.4309) radius 2.159
  circle C7 centre (-18.76, -36.96) radius 1
  circle C8 centre (18.76, 36.96) radius 1
  circle C9 centre (-31.4309, 31.4309) radius 2.159
  circle C10 centre (0, 0) radius 5
  circle C11 centre (-36.96, 18.76) radius 1
  circle C12 centre (36.96, 18.76) radius 1
  circle C13 centre (-36.96, -18.76) radius 1
  arc A13 centre (5.1796, -5.1796) radius 14.4414 clockwise from (12.6119, 7.2025) to (17.5616, 2.2528)
  arc A14 centre (17.5539, 7.1948) radius 3.5 clockwise from (15.0791, 9.6697) to (20.0288, 4.7199)
  circle C14 centre (17.5539, 7.1948) radius 2
  arc A15 centre (5.1796, -5.1796) radius 14 clockwise from (-1.3868, -17.5442) to (-7.185, -11.7459)
  arc A16 centre (5.1796, -5.1796) radius 14 clockwise from (6.235, -19.1397) to (-1.3868, -17.5442)
  arc A17 centre (5.1796, -5.1796) radius 14 clockwise from (8.0318, -18.8859) to (6.235, -19.1397)
  closed curve K3 centre (5.1796, -5.1796)
  arc A18 centre (5.1796, -5.1796) radius 14 clockwise from (18.7748, -8.5217) to (8.5217, -18.7748)
  closed curve K4 centre (5.1796, -5.1796)
  arc A19 centre (5.1796, -5.1796) radius 14 clockwise from (19.1397, -6.235) to (18.8859, -8.0318)
  arc A20 centre (5.1796, -5.1796) radius 14 clockwise from (17.5442, 1.3868) to (19.1397, -6.235)
  arc A21 centre (5.1796, -5.1796) radius 14 clockwise from (11.7459, 7.185) to (17.5442, 1.3868)
  arc A22 centre (5.1796, -5.1796) radius 14 clockwise from (-0.4826, 7.6244) to (11.7459, 7.185)
  arc A23 centre (5.1796, -5.1796) radius 14 clockwise from (-7.6244, 0.4826) to (-0.4826, 7.6244)
  arc A24 centre (5.1796, -5.1796) radius 14 clockwise from (-7.185, -11.7459) to (-7.6244, 0.4826)
  circle C15 centre (5.1796, -5.1796) radius 14
  arc A25 centre (5.1796, -5.1796) radius 14.4414 clockwise from (-2.2528, -17.5616) to (-7.2025, -12.6119)
  arc A26 centre (-7.1948, -17.5539) radius 3.5 clockwise from (-4.7199, -20.0288) to (-9.6697, -15.0791)
  circle C16 centre (-7.1948, -17.5539) radius 2
pipe "Pipe1" SectionSize 0.5 SectionThickness 0.109
pipe "Pipe2" SectionSize 0.5 SectionThickness 0.125
sketch "Sketch2" plane through (0, -11.25, 0) normal (0, -1, 0) x axis (1, 0, 0)
  line L1 (-36.3096, -14.7229) -> (-36.3096, -14.4805)
  line L2 (-40.0857, -22.5033) -> (-36.8335, -18.2363)
  line L3 (-18.2363, -36.8335) -> (-22.5033, -40.0857)
  line L4 (-14.4805, -36.3096) -> (-14.7229, -36.3096)
  line L5 (-40.9575, -25.2062) -> (-40.9575, -24.9738)
  line L6 (-24.9738, -40.9575) -> (-25.2062, -40.9575)
  line L7 (-11.883, -36.8176) -> (-12.0286, -36.8176)
  line L8 (-36.8176, -12.0286) -> (-36.8176, -11.883)
  circle C1 centre (-30.9024, -30.9024) radius 3.25
  arc A1 centre (0, 0) radius 39.0906 clockwise from (-36.3096, -14.4805) to (-14.4805, -36.3096)
  arc A2 centre (-39.7627, -16.0038) radius 3.683 clockwise from (-36.3096, -14.7229) to (-36.8335, -18.2363)
  arc A3 centre (0, 0) radius 48.7172 clockwise from (-27.4986, -40.2143) to (-40.2143, -27.4986)
  arc A4 centre (-16.0038, -39.7627) radius 3.683 clockwise from (-18.2363, -36.8335) to (-14.7229, -36.3096)
  circle C2 centre (-36, -23) radius 2.25
  circle C3 centre (-36, -23) radius 2.125
  arc A5 centre (-36.6919, -25.09) radius 4.2672 clockwise from (-40.9575, -24.9738) to (-40.0857, -22.5033)
  arc A6 centre (-36.6919, -25.09) radius 4.2672 clockwise from (-40.2143, -27.4986) to (-40.9575, -25.2062)
  arc A7 centre (-25.09, -36.6919) radius 4.2672 clockwise from (-25.2062, -40.9575) to (-27.4986, -40.2143)
  arc A8 centre (-25.09, -36.6919) radius 4.2672 clockwise from (-22.5033, -40.0857) to (-24.9738, -40.9575)
  arc A9 centre (0, 0) radius 38.6878 clockwise from (-11.883, -36.8176) to (-36.8176, -11.883)
  arc A10 centre (0, 0) radius 38.7327 clockwise from (-36.8176, -12.0286) to (-12.0286, -36.8176)
  point P1 (0, 0)
  point P16 (-36, -23)
  concentric C2 C3
  dimension "d324" diameter C2 = 4.5
  dimension "d325" distance P1 P16 = 36
  dimension "d326" distance P1 P16 = 23
  dimension "d347" distance C2 C3 = 0.125
extrude "Extrude5" cut sketch "Sketch2" profile of C2 C3 against normal blind 0.5
fillet "Fillet1" radius 0.15
sketch "Sketch3" plane through (0, -11.25, 0) normal (0, -1, 0) x axis (1, 0, 0)
  line L1 (-36.25, -25.2021) -> (-35.75, -25.2021)
  line L2 (-36.25, -20.7979) -> (-36.25, -25.2021)
  line L3 (-35.75, -20.7979) -> (-36.25, -20.7979)
  line L4 (-35.75, -25.2021) -> (-35.75, -20.7979)
  line L5 (-36.25, -20.7979) -> (-35.75, -25.2021)
  line L6 (-35.75, -20.7979) -> (-36.25, -25.2021)
  circle C1 centre (-36, -23) radius 1.975
  circle C2 centre (-36, -22.5) radius 1.25
  point P7 (-36, -23)
  point P2 (-36, -23)
  horizontal L1
  perpendicular L1 L2
  parallel L1 L3
  parallel L2 L4
  coincident L5 P7
  coincident L6 P7
  coincident P2 P7
  dimension "d332" distance L2 L4 = 0.5
extrude "Extrude6" cut sketch "Sketch3" profile of C1 L1 L2 L3 L4 C2 to an object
